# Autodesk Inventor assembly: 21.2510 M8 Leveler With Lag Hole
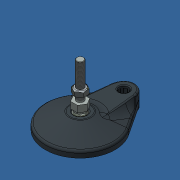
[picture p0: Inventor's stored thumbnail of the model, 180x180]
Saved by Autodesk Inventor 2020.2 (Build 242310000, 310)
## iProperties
Created: 2015-09
Part Number: 21.2510 M8 Leveler With Lag Hole
Description: Gelenkfuß M08 D 80 mit einer Befestigungsbohrung
Document SubType Name: Assembly
Designer: MuellerJ
Mass: 115.137 g
Surface Area: 333.955 cm^2
Volume: 71.0988 cm^3
Density: 1.6194 g/cm^3
Beschreibung: Gelenkfuß M08 D 80 mit einer Befestigungsbohrung
Bezeichnung: Gelenkfuß M08 D 80 mit einer Befestigungsbohrung
Artikelnr: 212510/0
Lieferantennr: 72401
Zeichnungsnr: leer
MiniTec_ID: 212510/0
Teileart: BK
Lieferant: MiniTec
Title: Gelenkfuß M08 D 80 mit einer Befestigungsbohrung
Author: MuellerJ
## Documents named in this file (5)
- Y:\INVENTOR LIBRARIES\PARTS LIBRARY\FEET WHEELS FLOOR FASTENING SUPPORTS\21.2510 M8 Leveler With Lag Hole.iam
- Y:\INVENTOR LIBRARIES\PARTS LIBRARY\FEET WHEELS FLOOR FASTENING SUPPORTS\SUBCOMPONENTS\LEVELING FEET SUBCOMPONENTS\21.2510 RUBBER PAD.ipt
- Y:\INVENTOR LIBRARIES\PARTS LIBRARY\FEET WHEELS FLOOR FASTENING SUPPORTS\SUBCOMPONENTS\LEVELING FEET SUBCOMPONENTS\21.2510 M8 STUD.ipt
- Y:\INVENTOR LIBRARIES\PARTS LIBRARY\FEET WHEELS FLOOR FASTENING SUPPORTS\SUBCOMPONENTS\LEVELING FEET SUBCOMPONENTS\21.2510 PLASTIC PAD.ipt
- Y:\INVENTOR LIBRARIES\PARTS LIBRARY\FASTENING ELEMENTS\NUTS\21.1526 M8 HEX NUT.ipt
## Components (4 placed, 4 different names)
1. 21.2510 PLASTIC PAD — Passend:2, Passend:3, Passend:4, Passend:6, Passend:7, Passend:8
2. 21.2510 RUBBER ANTI SKID PAD — Passend:2, Passend:3, Passend:4
3. 21.2510 M8 STUD — Passend:6, Passend:7, Passend:8, Mate:9, Mate:10
4. 21.1526 M8 HEX NUT:1 — Mate:9, Mate:10
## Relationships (8: Mate 8)
- Passend:2 [Mate]: 21.2510 PLASTIC PAD ↔ 21.2510 RUBBER ANTI SKID PAD
- Passend:3 [Mate]: 21.2510 PLASTIC PAD ↔ 21.2510 RUBBER ANTI SKID PAD
- Passend:4 [Mate]: 21.2510 PLASTIC PAD ↔ 21.2510 RUBBER ANTI SKID PAD
- Passend:6 [Mate]: 21.2510 PLASTIC PAD ↔ 21.2510 M8 STUD
- Passend:7 [Mate]: 21.2510 PLASTIC PAD ↔ 21.2510 M8 STUD
- Passend:8 [Mate]: 21.2510 PLASTIC PAD ↔ 21.2510 M8 STUD
- Mate:9: 21.2510 M8 STUD ↔ 21.1526 M8 HEX NUT:1
- Mate:10: 21.2510 M8 STUD ↔ 21.1526 M8 HEX NUT:1
